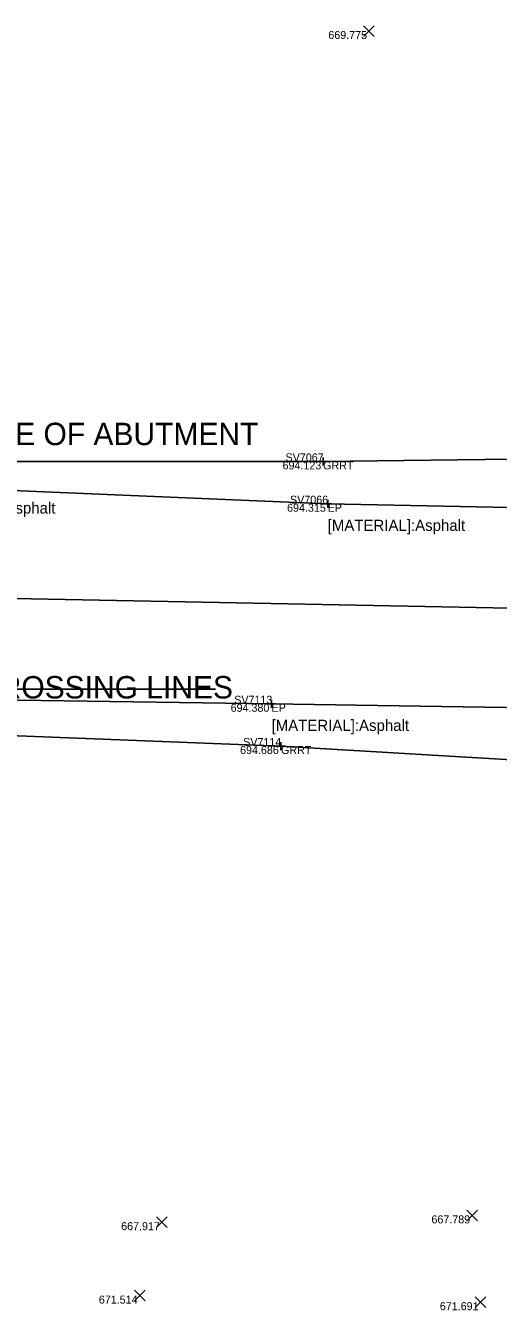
# Model space of a CAD drawing. Extents: x 1659932 to 1663108, y 619867 to 620611.
# Drawn here: x 1661564.7 to 1661623.8, y 620138.5 to 620299.1 of the extents above; entities that cross this region are included whole.
import ezdxf

# ---------------------------------------------------------------- set-up
doc = ezdxf.new("R2010")
doc.units = 0
for name, color, linetype in [('PM_X_CL_Dashed', 7, 'Continuous'), ('PV_X_EOP', 7, 'Continuous'), ('RD_X_GR_Rt', 7, 'Continuous'), ('SC_Scratch6', 7, 'Continuous'), ('SV_X_Random_Point', 7, 'Continuous'), ('SV_X_Shot_Marker', 7, 'Continuous'), ('SV_X_Text', 7, 'Continuous'), ('SV_X_Text_Comment', 7, 'Continuous'), ('SV_X_Text_Elevation', 7, 'Continuous'), ('SV_X_Text_Name', 7, 'Continuous')]:
    doc.layers.add(name, color=color, linetype=linetype)

msp = doc.modelspace()

# ---------------------------------------------------------------- linework, layer by layer
at = {"layer": 'PM_X_CL_Dashed'}
msp.add_lwpolyline([(1661548.68, 620227.77), (1661669.96, 620225.42), (1661783.14, 620222.83), (1661893.22, 620220.99), (1661995.64, 620218.69), (1662098.65, 620216.83), (1662208.49, 620214.49), (1662310.47, 620212.73), (1662401.36, 620210.77), (1662501.77, 620209.17), (1662614.52, 620207.13), (1662727.83, 620205.67), (1662841.02, 620204.32), (1662955.43, 620202.56), (1663049.21, 620201.36)], dxfattribs=at)
at = {"layer": 'PV_X_EOP'}
for points in [[(1662111.67, 620229.32), (1662054.93, 620230.37), (1661998.42, 620231.32), (1661945.73, 620232.16), (1661885.47, 620233.5), (1661831.11, 620234.65), (1661773.24, 620235.9), (1661719.2, 620236.82), (1661662.34, 620238.11), (1661602.46, 620239.35), (1661551.29, 620241.52)], [(1661543.6, 620215.08), (1661595.45, 620214.35), (1661653.94, 620213.41), (1661707.72, 620212.24), (1661760.97, 620211.02), (1661840.69, 620209.32), (1661897.28, 620208.31), (1661955.8, 620207.5), (1662009.84, 620206.22), (1662063.33, 620205.17), (1662115.71, 620204.21)]]:
    msp.add_lwpolyline(points, dxfattribs=at)
at = {"layer": 'RD_X_GR_Rt'}
for points in [[(1662112.15, 620237.06), (1662055.66, 620238.25), (1661999.68, 620239.27), (1661943.73, 620240.2), (1661887.33, 620241.47), (1661831.01, 620242.22), (1661774.89, 620243.8), (1661718.6, 620244.37), (1661662.44, 620245.38), (1661601.89, 620244.64), (1661537.84, 620244.62)], [(1661527.71, 620211.76), (1661596.63, 620209.07), (1661652.77, 620205.71), (1661709.09, 620204.45), (1661758.9, 620203.47), (1661840.54, 620201.81), (1661896.27, 620200.97), (1661955.33, 620199.48), (1662008.56, 620198.59), (1662063.03, 620197.38), (1662114.92, 620196.42)]]:
    msp.add_lwpolyline(points, dxfattribs=at)
at = {"layer": 'SC_Scratch6'}
msp.add_line((1661547.5, 620216.17), (1661588.46, 620216.17), dxfattribs=at)
at = {"layer": 'SV_X_Random_Point'}
for p, q in [((1661606.95, 620297.76), (1661608.28, 620299.09)), ((1661606.95, 620299.09), (1661608.28, 620297.76)), ((1661619.83, 620149.74), (1661621.17, 620151.07)), ((1661619.83, 620151.07), (1661621.17, 620149.74)), ((1661581.09, 620148.89), (1661582.43, 620150.23)), ((1661581.09, 620150.23), (1661582.43, 620148.89)), ((1661578.33, 620139.72), (1661579.67, 620141.05)), ((1661578.33, 620141.05), (1661579.67, 620139.72)), ((1661620.89, 620138.89), (1661622.22, 620140.23)), ((1661620.89, 620140.23), (1661622.22, 620138.89))]:
    msp.add_line(p, q, dxfattribs=at)
at = {"layer": 'SV_X_Shot_Marker'}
for p, q in [((1661601.39, 620244.64), (1661602.39, 620244.64)), ((1661601.89, 620245.14), (1661601.89, 620244.14)), ((1661601.89, 620244.64), (1661601.89, 620244.64)), ((1661601.96, 620239.35), (1661602.96, 620239.35)), ((1661602.46, 620239.85), (1661602.46, 620238.85)), ((1661602.46, 620239.35), (1661602.46, 620239.35)), ((1661594.95, 620214.35), (1661595.95, 620214.35)), ((1661595.45, 620214.85), (1661595.45, 620213.85)), ((1661595.45, 620214.35), (1661595.45, 620214.35)), ((1661596.13, 620209.07), (1661597.13, 620209.07)), ((1661596.63, 620209.57), (1661596.63, 620208.57)), ((1661596.63, 620209.07), (1661596.63, 620209.07))]:
    msp.add_line(p, q, dxfattribs=at)

# ---------------------------------------------------------------- texts
at = {"layer": 'SC_Scratch6'}
for s, p in [('MISSING OUTLINE OF ABUTMENT', (1661532.85, 620246.67)), ('FIX CROSSING LINES', (1661551.93, 620215.01))]:
    msp.add_text(s, height=2.8, dxfattribs=at).set_placement(p)
at = {"layer": 'SV_X_Text'}
for p in [(1661551.29, 620238.12), (1661602.46, 620235.95), (1661595.45, 620210.95)]:
    msp.add_text('[MATERIAL]:Asphalt', height=1.4, dxfattribs=at).set_placement(p)
at = {"layer": 'SV_X_Text_Comment'}
for s, p in [('GRRT', (1661601.89, 620243.64)), ('EP', (1661602.46, 620238.35)), ('EP', (1661595.45, 620213.35)), ('GRRT', (1661596.63, 620208.07))]:
    msp.add_text(s, height=1, dxfattribs=at).set_placement(p)
at = {"layer": 'SV_X_Text_Elevation'}
for s, p in [('669.775', (1661602.54, 620297.43)), ('694.123', (1661596.83, 620243.64)), ('694.315', (1661597.39, 620238.35)), ('694.380', (1661590.34, 620213.35)), ('694.686', (1661591.52, 620208.07)), ('667.917', (1661576.67, 620148.56)), ('667.789', (1661615.42, 620149.41)), ('671.514', (1661573.88, 620139.38)), ('671.691', (1661616.47, 620138.56))]:
    msp.add_text(s, height=1, dxfattribs=at).set_placement(p)
at = {"layer": 'SV_X_Text_Name'}
for s, p in [('SV7067', (1661597.2, 620244.64)), ('SV7066', (1661597.76, 620239.35)), ('SV7113', (1661590.79, 620214.35)), ('SV7114', (1661591.91, 620209.07))]:
    msp.add_text(s, height=1, dxfattribs=at).set_placement(p)

doc.saveas('drawing.dxf')
